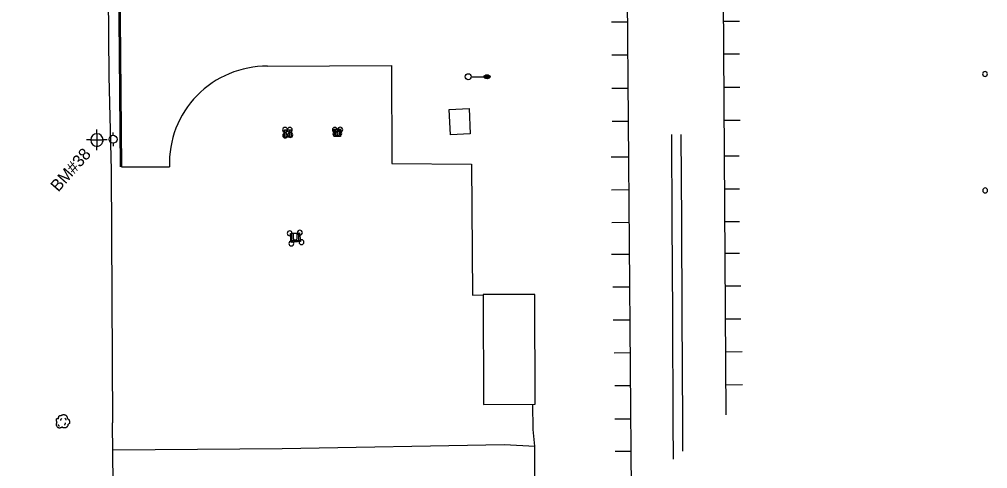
# Model space of a CAD drawing. Extents: x 2145380 to 2156929, y 139568 to 149130.
# Drawn here: x 2151746.9 to 2152234.1, y 142047.3 to 142273.5 of the extents above; entities that cross this region are included whole.
import ezdxf

# ---------------------------------------------------------------- set-up
doc = ezdxf.new("R2010")
doc.units = 0
for name, color, linetype in [('SURV_Benchmark', 7, 'Continuous'), ('SURV_Text', 7, 'Continuous'), ('TOPO_Asphalt', 7, 'Continuous'), ('TOPO_Building', 7, 'Continuous'), ('TOPO_Curb Back', 7, 'Continuous'), ('TOPO_Dirt Grav', 7, 'Continuous'), ('TOPO_Fence', 7, 'Continuous'), ('TOPO_Light Pole', 7, 'Continuous'), ('TOPO_Misc', 7, 'Continuous'), ('TOPO_Misc Line', 7, 'Continuous'), ('TOPO_Power Pole', 7, 'Continuous'), ('TOPO_RR Rail', 7, 'Continuous'), ('TOPO_Tree', 7, 'Continuous'), ('TOPO_Wall Freestanding', 7, 'Continuous')]:
    doc.layers.add(name, color=color, linetype=linetype)

# ---------------------------------------------------------------- blocks, each defined once
blk = doc.blocks.new('POST')
at = {"layer": 'TOPO_Misc'}
for start, end in [(90, 180), (180, 270), (360, 90), (270, 0)]:
    blk.add_arc((0, 0), 3.16, start, end, dxfattribs=at)
blk = doc.blocks.new('POWPOL')
at = {"layer": 'TOPO_Power Pole'}
for p, q in [((0, 10.2), (0, 17.3)), ((0, -10.2), (0, -17.3))]:
    blk.add_line(p, q, dxfattribs=at)
blk.add_circle((0, 0), 10.2, dxfattribs=at)
blk = doc.blocks.new('LP')
at = {"layer": 'TOPO_Light Pole'}
blk.add_line((3.8, 0), (20.3, 0), dxfattribs=at)
for points in [[(20.3, 0), (27.9, 0)], [(20.3, 0), (23.5, 0)], [(20.8, 1.3), (27.4, 1.3)], [(20.8, 1.3), (23.5, 1.3)], [(23.7, 1.3), (27.4, 1.3)], [(23.7, 0), (27.9, 0)], [(20.8, -1.3), (27.4, -1.3)], [(20.8, -1.3), (23.5, -1.3)], [(23.7, -1.3), (27.4, -1.3)]]:
    blk.add_lwpolyline(points, dxfattribs=at)
blk.add_circle((0, 0), 3.81, dxfattribs=at)
blk.add_ellipse((24.1, 0), major_axis=(3.81, 0), ratio=0.666667, dxfattribs=at)
blk = doc.blocks.new('TREE')
at = {"layer": 'TOPO_Tree'}
for points in [[(-14.1, -0.4), (-14.2, 0.5), (-14.4, 1.4), (-14.6, 2.3), (-14.8, 3.2), (-15.5, 4), (-15.7, 4.9), (-15.8, 5.6), (-15.7, 6.3), (-15.7, 7), (-15.6, 7.9), (-15.7, 8.8), (-15.1, 9.7), (-14.6, 10.4), (-13.8, 10.5), (-13, 10.7), (-12.2, 11), (-11.1, 10), (-10.4, 10.7), (-9.4, 11.7), (-10.3, 13.3), (-9.8, 14.4), (-9.6, 15.1), (-9.3, 15.9), (-8.8, 16.5), (-8.2, 17.3), (-7.5, 17.7), (-6.7, 18.1), (-6.1, 18.4), (-5.6, 18.6), (-5.1, 18.7), (-4.5, 18.7), (-4, 18.5), (-3.5, 18.1)], [(13.2, -5.3), (13.3, -5.8), (13.4, -6.3), (13.4, -6.7), (13.8, -8.5), (12.2, -10), (10.8, -11.5), (10, -12.3), (9.1, -12.8), (8.2, -13.1), (6, -13.8), (3.3, -13.6), (1.3, -13.1), (0.5, -12.9), (-0.1, -11.4), (-0.8, -11.5), (-2, -11.6), (-3.3, -12.8), (-4.5, -13.1), (-6.1, -13.5), (-7.8, -14), (-9.3, -13.6), (-11.4, -13.1), (-12.8, -11.4), (-14.1, -9.4), (-15.3, -7.3), (-15.6, -5.1), (-15.1, -3), (-14.9, -1.9), (-13.9, -0.8), (-13.5, 0.1)], [(-4.2, 5.1), (-4.5, 6.1), (-4.3, 7.2), (-3.8, 8.2), (-3.3, 9.3), (-2.7, 10.3), (-1.6, 11)], [(-3.5, 17.6), (-3.1, 18.3), (-2.6, 18.8), (-1.9, 19.2), (-1, 19.7), (-0.2, 20), (0.7, 20.2), (1.6, 20.5), (2.5, 20.8), (3.4, 20.8), (4.1, 20.7), (4.8, 20.5), (5.5, 20.2), (6.4, 19.9), (7.3, 19.7), (8.2, 19.2), (9.4, 18.4), (10, 17.2), (10.8, 16), (11.2, 15.3), (11.6, 14.6), (11.9, 13.9), (12.2, 13.1), (11.4, 12), (11.9, 11.2), (12, 11), (12.2, 10.9), (12.4, 10.7), (12.9, 10.4), (13.5, 10), (14, 9.7), (14.7, 9.2), (15.4, 8.7), (16.1, 8.1), (16.7, 7.5), (16.9, 6.7), (17.1, 6), (17.6, 4.4), (17.7, 2.8), (17.7, 1.2), (17.7, -0.2), (17.8, -2.2), (16.6, -3), (15.5, -3.8), (14.3, -4.6), (13.2, -5.3)], [(5.9, 11.2), (6.5, 10.7), (7, 10.2), (7.4, 9.5), (7.9, 8.6), (8.3, 7.6), (8.5, 6.6)], [(-11.4, -4.5), (-11.5, -5.4), (-11, -6.3), (-10.1, -7.2), (-9.3, -8), (-8.5, -8.3), (-7.7, -8.1)], [(4.8, -6.3), (5.7, -5.7), (6.3, -4.9), (6.8, -3.9), (7.4, -2.8), (7.6, -1.7), (7.5, -0.6)]]:
    blk.add_open_spline(points, degree=3, dxfattribs=at)
blk = doc.blocks.new('BM')
at = {"layer": 'SURV_Benchmark'}
for p, q in [((0, 2.49), (0, 4.15)), ((-2.49, 0), (-4.16, 0)), ((4.16, 0), (2.49, 0)), ((0, -4.16), (0, -2.49))]:
    blk.add_line(p, q, dxfattribs=at)
for points in [[(-2.5, 0), (-2.49, 0), (0, 0), (0, -2.49), (0, -2.49)], [(-2.5, 0), (-2.49, 0), (0, 0), (0, -2.49), (0, -2.49)], [(0, 2.49), (0, 2.49), (0, 0), (2.49, 0), (2.49, 0), (2.49, 0)], [(0, 2.49), (0, 2.49), (0, 0), (2.49, 0), (2.49, 0), (2.49, 0), (2.49, 0)]]:
    blk.add_lwpolyline(points, dxfattribs=at)
for start, end in [(90.0638, 180.0068), (0.0638, 90.0068), (0.0638, 90.0068), (180.0638, 270.0068), (180.0638, 270.0068), (269.9472, 359.9927)]:
    blk.add_arc((0, 0), 2.5, start, end, dxfattribs=at)

msp = doc.modelspace()

# ---------------------------------------------------------------- linework, layer by layer
at = {"layer": 'TOPO_Asphalt'}
for points in [[(2151871.73, 142249.92), (2151934.18, 142250.24), (2151934.25, 142200.9), (2151974.46, 142200.58), (2151974.84, 142134.69), (2151980.24, 142134.81)], [(2151798.31, 142199.23), (2151822.37, 142199.34)], [(2152006.15, 141993.62), (2152006.18, 142058.62), (2152005.49, 142066.97), (2152005.17, 142079.73)]]:
    msp.add_lwpolyline(points, dxfattribs=at)
msp.add_arc((2151871.36, 142200.92), 49.01, 89.5645, 181.8476, dxfattribs=at)
at = {"layer": 'TOPO_Building'}
for points in [[(2151973.15, 142228.65), (2151973.74, 142215.84), (2151963.75, 142215.38), (2151963.16, 142228.18)], [(2151980.34, 142134.96), (2151980.45, 142079.68), (2152006.43, 142079.73), (2152006.32, 142135.01)]]:
    msp.add_lwpolyline(points, close=True, dxfattribs=at)
at = {"layer": 'TOPO_Curb Back'}
for points in [[(2151793.45, 142667.52), (2151793.5, 142664.11), (2151793.97, 142609.49), (2151794.94, 142514.55), (2151795.62, 142434.05), (2151796.05, 142363.7), (2151796.95, 142274.01), (2151797.69, 142199.22)], [(2151794.06, 142667.33), (2151794.1, 142664.12), (2151794.57, 142609.49), (2151795.54, 142514.55), (2151796.22, 142434.05), (2151796.65, 142363.71), (2151797.55, 142274.02), (2151798.29, 142199.23)]]:
    msp.add_lwpolyline(points, dxfattribs=at)
at = {"layer": 'TOPO_Dirt Grav'}
msp.add_lwpolyline([(2151793.87, 142056.76), (2151879.16, 142057.46), (2151991.01, 142059.54), (2152006.18, 142058.62)], dxfattribs=at)
at = {"layer": 'TOPO_Fence'}
for points in [[(2152156.3, 142727.8), (2152037.55, 142726.76), (2151920.89, 142726.41), (2151852.64, 142725.44), (2151853.17, 142668.35), (2151806.44, 142666.81), (2151805.3, 142722.8), (2151788.15, 142722.54), (2151788.95, 142630.15), (2151790.48, 142506.16), (2151790.71, 142388.22), (2151791.87, 142244.89), (2151793.13, 142197.34), (2151793.71, 142070.44)], [(2151795.99, 141817.22), (2151795.25, 141933.82), (2151793.71, 142070.44)]]:
    msp.add_lwpolyline(points, dxfattribs=at)
at = {"layer": 'TOPO_Misc'}
for p, q in [((2152044.85, 142272.18), (2152052.87, 142272.23)), ((2152101.25, 142272.53), (2152109.31, 142272.58)), ((2152053.01, 142255.51), (2152044.92, 142255.44)), ((2152109.29, 142256), (2152101.35, 142255.93)), ((2152109.35, 142239.23), (2152101.18, 142239.16)), ((2152053.15, 142238.74), (2152044.98, 142238.67)), ((2152053.29, 142222.11), (2152045.17, 142222.04)), ((2152109.54, 142222.6), (2152101.29, 142222.53)), ((2151880.92, 142217.46), (2151880.92, 142215.05)), ((2151882.99, 142215.06), (2151882.99, 142217.47)), ((2151905.84, 142217.8), (2151905.84, 142215.39)), ((2151907.91, 142215.4), (2151907.91, 142217.81)), ((2152053.44, 142204.2), (2152044.68, 142204.13)), ((2152109.05, 142204.69), (2152101.4, 142204.62)), ((2152053.58, 142187.62), (2152044.86, 142187.54)), ((2152109.23, 142188.1), (2152101.5, 142188.04)), ((2152053.72, 142171.17), (2152044.92, 142171.09)), ((2152109.29, 142171.65), (2152101.61, 142171.59)), ((2151884.61, 142165.36), (2151884.61, 142162.95)), ((2151886.69, 142162.96), (2151886.69, 142165.37)), ((2152053.85, 142155.22), (2152044.87, 142155.14)), ((2152109.24, 142155.7), (2152101.71, 142155.63)), ((2152053.99, 142138.7), (2152045.56, 142138.63)), ((2152109.93, 142139.19), (2152101.81, 142139.12)), ((2152054.13, 142122.14), (2152045.59, 142122.06)), ((2152109.96, 142122.62), (2152101.92, 142122.55)), ((2152054.27, 142105.58), (2152046.24, 142105.51)), ((2152110.61, 142106.07), (2152102.02, 142106)), ((2152054.41, 142089.01), (2152046.45, 142088.94)), ((2152110.82, 142089.5), (2152102.12, 142089.42)), ((2152054.55, 142072.28), (2152046.44, 142072.21)), ((2152054.68, 142055.98), (2152046.6, 142055.91))]:
    msp.add_line(p, q, dxfattribs=at)
for points in [[(2151880.33, 142214.14), (2151880.33, 142217.91), (2151883.59, 142217.91), (2151883.59, 142214.14), (2151880.33, 142214.14)], [(2151905.25, 142214.48), (2151905.25, 142218.24), (2151908.51, 142218.24), (2151908.51, 142214.48), (2151905.25, 142214.48)], [(2151884.03, 142162.05), (2151884.03, 142165.81), (2151887.29, 142165.81), (2151887.29, 142162.05), (2151884.03, 142162.05)]]:
    msp.add_lwpolyline(points, dxfattribs=at)
for centre in [(2151881.95, 142215.87), (2151906.87, 142216.21), (2151885.65, 142163.77)]:
    msp.add_arc(centre, 1.32, 218.3412, 322.0625, dxfattribs=at)
at = {"layer": 'TOPO_Misc Line'}
for p, q in [((2152052.12, 142354.6), (2152054.73, 142034.39)), ((2152102.5, 142074.49), (2152100.72, 142354.98))]:
    msp.add_line(p, q, dxfattribs=at)
at = {"layer": 'TOPO_RR Rail'}
for points in [[(2152074.96, 142215.52), (2152075.26, 142171.59), (2152075.49, 142124.76), (2152075.73, 142070.77), (2152075.85, 142052.11)], [(2152079.76, 142215.56), (2152080.06, 142171.62), (2152080.29, 142124.78), (2152080.53, 142070.8), (2152080.62, 142056.12)]]:
    msp.add_lwpolyline(points, dxfattribs=at)
at = {"layer": 'TOPO_Tree'}
msp.add_open_spline([(2151780.83, 142727.26), (2151780.78, 142724.91), (2151780.73, 142722.56), (2151780.68, 142720.2), (2151780.66, 142719.27), (2151780.8, 142718.34), (2151780.81, 142717.4), (2151780.83, 142716.32), (2151780.7, 142715.23), (2151780.73, 142714.15), (2151780.77, 142712.16), (2151780.92, 142710.18), (2151781, 142708.19), (2151781.07, 142706.45), (2151781.43, 142704.69), (2151781.05, 142702.97), (2151780.64, 142701.13), (2151779.99, 142699.41), (2151779.43, 142697.64), (2151778.7, 142695.3), (2151777.94, 142692.97), (2151777.22, 142690.63), (2151776.03, 142686.81), (2151775.24, 142682.9), (2151774.36, 142678.99), (2151773.49, 142675.07), (2151772.82, 142670.97), (2151773.21, 142667.03), (2151773.31, 142665.99), (2151773.74, 142664.99), (2151774.14, 142663.99), (2151774.46, 142663.21), (2151774.95, 142662.54), (2151775.24, 142661.74), (2151775.68, 142660.57), (2151775.86, 142659.35), (2151776, 142658.14), (2151776.2, 142656.32), (2151776.05, 142654.44), (2151775.68, 142652.6), (2151775.45, 142651.46), (2151775.13, 142650.41), (2151774.06, 142649.58), (2151772.64, 142648.47), (2151771.14, 142648.56), (2151769.66, 142648.42), (2151768.75, 142648.33), (2151767.54, 142647.89), (2151766.88, 142648.75), (2151765.83, 142650.11), (2151765.98, 142651.58), (2151765.45, 142652.97), (2151764.84, 142654.58), (2151764.24, 142656.19), (2151763.62, 142657.8), (2151762.37, 142661.02), (2151761.09, 142664.22), (2151759.78, 142667.42), (2151758.8, 142669.83), (2151757.46, 142672.09), (2151756.43, 142674.48), (2151755.1, 142677.56), (2151754.31, 142680.85), (2151753.1, 142684), (2151752.02, 142686.84), (2151750.95, 142689.65), (2151749.1, 142692.16), (2151748.39, 142693.12), (2151747.48, 142693.82), (2151746.55, 142694.53), (2151744.99, 142695.73), (2151743.31, 142696.75), (2151741.77, 142697.96), (2151738.39, 142700.65), (2151735.61, 142704.02), (2151732.23, 142706.78), (2151729.46, 142709.03), (2151726.58, 142711.31), (2151723.19, 142712.37), (2151720.79, 142713.13), (2151718.36, 142713.71), (2151715.96, 142714.41), (2151713.39, 142715.17), (2151710.93, 142716.14), (2151708.26, 142716.76), (2151706.47, 142717.18), (2151704.67, 142716.99), (2151702.86, 142717.01), (2151701.07, 142717.03), (2151699.27, 142716.74), (2151697.48, 142716.92), (2151691.85, 142717.47), (2151686.4, 142719.1), (2151680.83, 142719.94), (2151677.09, 142720.51), (2151673.37, 142721.18), (2151669.6, 142721.48), (2151665.19, 142721.82), (2151660.76, 142721.71), (2151656.35, 142721.9), (2151653.98, 142722), (2151651.6, 142722.62), (2151649.25, 142722.39), (2151647.81, 142722.25), (2151646.42, 142721.73), (2151644.99, 142721.45), (2151640.18, 142720.51), (2151635.32, 142719.69), (2151630.52, 142718.68), (2151627.61, 142718.06), (2151624.73, 142717.32), (2151621.85, 142716.6), (2151620.66, 142716.31), (2151619.49, 142715.93), (2151618.31, 142715.61), (2151616.13, 142715.03), (2151613.81, 142715.38), (2151611.58, 142714.87), (2151610.54, 142714.64), (2151609.45, 142714.15), (2151608.91, 142713.14), (2151607.73, 142710.91), (2151608.33, 142708.42), (2151607.62, 142706.18), (2151606.77, 142703.49), (2151605.54, 142700.91), (2151604.81, 142698.13), (2151604.2, 142695.79), (2151603.67, 142693.43), (2151603.67, 142691.04), (2151603.67, 142689.83), (2151603.78, 142688.62), (2151603.79, 142687.41), (2151603.81, 142685.87), (2151603.7, 142684.32), (2151603.77, 142682.77), (2151603.87, 142680.77), (2151604.26, 142678.78), (2151604.47, 142676.78), (2151604.59, 142675.63), (2151605, 142674.43), (2151604.69, 142673.31), (2151604.24, 142671.69), (2151603.52, 142670.16), (2151602.95, 142668.59), (2151602.07, 142666.15), (2151601.22, 142663.69), (2151600.34, 142661.25), (2151599.42, 142658.68), (2151596.86, 142656.77), (2151596.4, 142654.04), (2151595.91, 142651.1), (2151596.85, 142648.16), (2151596.8, 142645.23), (2151596.72, 142640.8), (2151596.89, 142636.37), (2151596.08, 142631.94), (2151595.83, 142630.55), (2151594.97, 142629.37), (2151594.61, 142628.02), (2151594.24, 142626.67), (2151593.87, 142625.3), (2151593.67, 142623.91), (2151593.29, 142621.25), (2151593.41, 142618.53), (2151592.98, 142615.88), (2151592.62, 142613.67), (2151592.25, 142611.47), (2151591.83, 142609.27), (2151591.58, 142607.99), (2151591.32, 142606.72), (2151591.07, 142605.45), (2151590.76, 142603.85), (2151590.55, 142602.24), (2151590.22, 142600.64), (2151589.75, 142598.32), (2151588.83, 142596.11), (2151588.07, 142593.88), (2151587.01, 142590.79), (2151584.27, 142588.07), (2151584.31, 142584.79), (2151584.33, 142582.55), (2151584.41, 142580.3), (2151584.46, 142578.05), (2151584.56, 142572.9), (2151584.64, 142567.76), (2151584.76, 142562.61), (2151584.84, 142558.6), (2151586.11, 142554.68), (2151586.32, 142550.67), (2151586.45, 142548.29), (2151586.54, 142545.92), (2151586.6, 142543.54), (2151586.75, 142536.73), (2151586.74, 142529.91), (2151586.92, 142523.09), (2151586.98, 142520.67), (2151587.15, 142518.25), (2151587.33, 142515.84), (2151587.58, 142512.51), (2151588.21, 142509.22), (2151588.58, 142505.9), (2151588.8, 142503.97), (2151589.27, 142501.95), (2151588.68, 142500.06), (2151588.31, 142498.88), (2151587.58, 142497.9), (2151587.11, 142496.79), (2151586.14, 142494.49), (2151585.17, 142492.19), (2151584.2, 142489.89), (2151583.51, 142488.27), (2151582.82, 142486.65), (2151582.13, 142485.04), (2151581.16, 142482.78), (2151580.02, 142480.61), (2151578.98, 142478.38), (2151578.06, 142476.41), (2151577.16, 142474.49), (2151576.44, 142472.39), (2151576.13, 142471.5), (2151576.11, 142470.56), (2151576.07, 142469.63), (2151575.99, 142467.63), (2151575.86, 142465.61), (2151576.07, 142463.61), (2151576.58, 142458.85), (2151577.31, 142454.11), (2151577.88, 142449.36), (2151578.03, 142448.08), (2151578.16, 142446.79), (2151578.27, 142445.51), (2151578.35, 142444.48), (2151577.33, 142443.5), (2151577.51, 142442.48), (2151577.79, 142440.98), (2151578.17, 142439.48), (2151578.45, 142437.97), (2151578.61, 142437.1), (2151578.77, 142436.23), (2151578.93, 142435.36), (2151579.12, 142434.34), (2151579.29, 142433.32), (2151579.39, 142432.3), (2151579.58, 142430.54), (2151579.12, 142428.78), (2151578.62, 142427.03), (2151578.18, 142425.45), (2151577.69, 142423.98), (2151577.02, 142422.51), (2151576.59, 142421.58), (2151576.11, 142420.69), (2151575.61, 142419.8), (2151575.11, 142418.91), (2151574.41, 142418.17), (2151573.92, 142417.25), (2151573.39, 142416.28), (2151573.08, 142415.23), (2151572.95, 142414.15), (2151572.84, 142413.28), (2151572.82, 142412.42), (2151572.82, 142411.55), (2151572.81, 142409.61), (2151572.96, 142407.66), (2151573.13, 142405.72), (2151573.27, 142404.13), (2151574.94, 142402.73), (2151574.9, 142401.28), (2151574.87, 142400.29), (2151573.54, 142399.47), (2151573.38, 142398.41), (2151572.9, 142395.21), (2151572.37, 142391.95), (2151572.26, 142388.69), (2151572.08, 142383.53), (2151571.93, 142378.37), (2151571.79, 142373.2), (2151571.75, 142371.54), (2151571.7, 142369.87), (2151571.73, 142368.21), (2151571.75, 142366.66), (2151572.44, 142365.19), (2151573.11, 142363.77), (2151573.71, 142362.51), (2151574.34, 142361.3), (2151575.02, 142360.1), (2151576.69, 142357.18), (2151578.62, 142354.43), (2151580.28, 142351.49), (2151582.14, 142348.22), (2151583.45, 142344.69), (2151584.81, 142341.22), (2151585.14, 142340.4), (2151585.01, 142339.43), (2151585.34, 142338.61), (2151585.75, 142337.61), (2151587.23, 142337.28), (2151587.59, 142336.26), (2151588.53, 142333.64), (2151589.43, 142330.99), (2151590.26, 142328.33), (2151593.59, 142317.58), (2151597.59, 142307.03), (2151600.08, 142296.05), (2151600.68, 142293.45), (2151601.13, 142290.82), (2151601.63, 142288.2), (2151602.35, 142284.42), (2151603.1, 142280.67), (2151603.73, 142276.86), (2151604.87, 142269.88), (2151605, 142262.81), (2151605.1, 142255.76), (2151605.12, 142254.4), (2151605.14, 142253.04), (2151605.15, 142251.68), (2151605.17, 142247.16), (2151605.09, 142242.63), (2151605.17, 142238.11), (2151605.25, 142233.35), (2151605.6, 142228.6), (2151605.88, 142223.84), (2151606.14, 142219.56), (2151606.44, 142215.28), (2151606.76, 142211.01), (2151606.9, 142209.19), (2151607.29, 142207.4), (2151607.36, 142205.59), (2151607.48, 142202.39), (2151607.32, 142199.19), (2151607.35, 142195.99), (2151607.39, 142191.29), (2151607.45, 142186.6), (2151607.64, 142181.91), (2151607.88, 142176.16), (2151609.93, 142170.59), (2151610.18, 142164.84), (2151610.24, 142163.41), (2151610.28, 142161.99), (2151610.32, 142160.56), (2151610.35, 142159.56), (2151610.41, 142158.56), (2151610.38, 142157.57), (2151610.3, 142154.59), (2151608.69, 142151.84), (2151608.01, 142148.94), (2151606.49, 142142.5), (2151605.06, 142136.03), (2151603.92, 142129.51), (2151603.43, 142126.69), (2151603.52, 142123.78), (2151603.73, 142120.93), (2151603.97, 142117.57), (2151604.85, 142114.29), (2151606.16, 142111.09), (2151606.81, 142109.5), (2151608.4, 142108.52), (2151609.02, 142106.94), (2151609.4, 142105.95), (2151609.72, 142104.95), (2151609.8, 142103.91), (2151610.55, 142093.22), (2151611.07, 142082.53), (2151611.48, 142071.84), (2151611.53, 142070.41), (2151611.62, 142068.98), (2151611.56, 142067.55), (2151611.41, 142063.95), (2151609.55, 142060.61), (2151608.91, 142057.05), (2151607.93, 142051.63), (2151606.51, 142046.21), (2151606.67, 142040.71), (2151606.71, 142039.19), (2151606.76, 142037.66), (2151606.8, 142036.13), (2151607.45, 142032.24), (2151608.1, 142028.35), (2151608.75, 142024.45), (2151610.81, 142019.62), (2151612.88, 142014.79), (2151614.95, 142009.96), (2151619.39, 142003.31), (2151623.83, 141996.65), (2151628.27, 141989.99), (2151631.86, 141984.42), (2151635.46, 141978.85), (2151639.05, 141973.28), (2151645.75, 141963.58), (2151652.45, 141953.88), (2151659.14, 141944.19), (2151664.08, 141930.99), (2151669.03, 141917.8), (2151673.97, 141904.61), (2151676.57, 141899.68), (2151679.16, 141894.75), (2151681.75, 141889.82), (2151683.3, 141880.14), (2151684.86, 141870.46), (2151686.41, 141860.78), (2151688.45, 141854.43), (2151690.49, 141848.09), (2151692.53, 141841.75), (2151695.79, 141834.96), (2151699.05, 141828.17), (2151702.31, 141821.38), (2151706.48, 141815.93), (2151710.65, 141810.48), (2151714.82, 141805.03), (2151723.4, 141793.58), (2151731.97, 141782.13), (2151740.55, 141770.68)], degree=3, dxfattribs=at)
at = {"layer": 'TOPO_Wall Freestanding'}
msp.add_lwpolyline([(2151883.37, 142165.73), (2151887.78, 142166.01), (2151888.28, 142161.72), (2151883.63, 142161.15)], close=True, dxfattribs=at)

# ---------------------------------------------------------------- block references
at = {"layer": 'SURV_Benchmark', "xscale": 1.25, "yscale": 1.25}
msp.add_blockref('BM', (2151785.92, 142212.8), dxfattribs=at)
at = {"layer": 'TOPO_Light Pole', "xscale": 0.39370000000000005, "yscale": 0.3937000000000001}
msp.add_blockref('LP', (2151972.72, 142244.62), dxfattribs=at)
at = {"layer": 'TOPO_Misc', "xscale": 0.39370000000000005, "yscale": 0.3937000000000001}
for p in [(2152232.76, 142246.02), (2151880.59, 142217.84), (2151880.65, 142215.06), (2151882.98, 142217.88), (2151883.24, 142215.32), (2151905.66, 142217.88), (2151905.88, 142215.88), (2151907.83, 142216.05), (2151908.34, 142217.99), (2152232.84, 142187.37), (2151882.92, 142165.78), (2151888.04, 142166.14), (2151883.72, 142160.71), (2151888.84, 142161.36)]:
    msp.add_blockref('POST', p, dxfattribs=at)
at = {"layer": 'TOPO_Power Pole', "xscale": 0.19685000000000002, "yscale": 0.19685000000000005}
msp.add_blockref('POWPOL', (2151794.03, 142213.16), dxfattribs=at)
at = {"layer": 'TOPO_Tree', "xscale": 0.19685000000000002, "yscale": 0.19685000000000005}
msp.add_blockref('TREE', (2151768.6, 142070.49), dxfattribs=at)

# ---------------------------------------------------------------- texts
at = {"layer": 'SURV_Text'}
msp.add_text('BM#38', height=6, rotation=48.5247, dxfattribs=at).set_placement((2151766.48, 142186.31))

doc.saveas('drawing.dxf')
